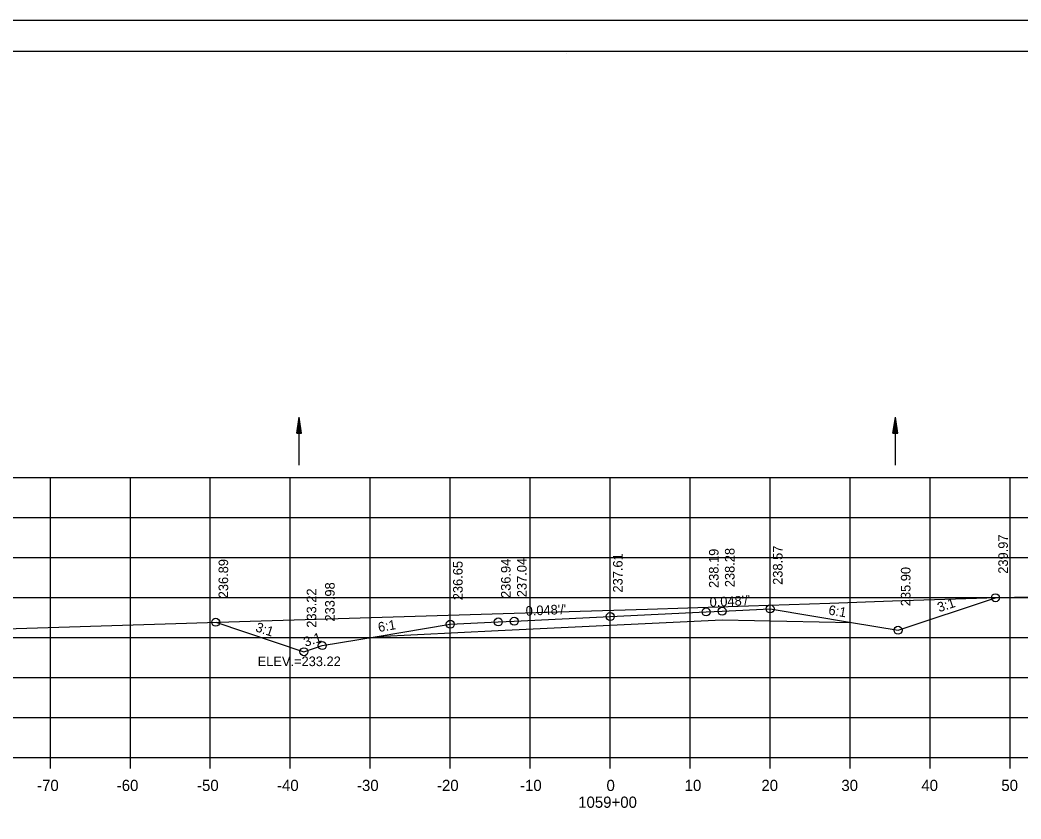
# Model space of a CAD drawing. Extents: x 1386544 to 1388153, y 379785 to 390999.
# Drawn here: x 1387285.9 to 1387411, y 388339 to 388438.9 of the extents above; entities that cross this region are included whole.
import ezdxf

# ---------------------------------------------------------------- set-up
doc = ezdxf.new("R2010")
doc.units = 0
for name, color, linetype in [('R_Alt Surface', 7, 'Continuous'), ('R_Axis', 7, 'Continuous'), ('R_Axis Annot', 7, 'Continuous'), ('R_Border', 7, 'Continuous'), ('R_Exist Surface', 7, 'Continuous'), ('R_Fin Surface', 7, 'Continuous'), ('R_Grid', 7, 'Continuous'), ('R_No Plot', 7, 'Continuous'), ('R_Water', 7, 'Continuous'), ('R_Xsect Elev', 7, 'Continuous'), ('R_Xsect Slope', 7, 'Continuous')]:
    doc.layers.add(name, color=color, linetype=linetype)

msp = doc.modelspace()

# ---------------------------------------------------------------- linework, layer by layer
at = {"layer": 'R_Alt Surface'}
msp.add_lwpolyline([(1387330.55, 388361.83), (1387345.68, 388362.55), (1387359.68, 388363.22), (1387373.68, 388363.9), (1387389.84, 388363.57)], dxfattribs=at)
at = {"layer": 'R_Axis'}
for p, q in [((1387209.68, 388346.7), (1387509.68, 388346.7)), ((1387289.68, 388345.3), (1387289.68, 388346.7)), ((1387299.68, 388345.3), (1387299.68, 388346.7)), ((1387309.68, 388345.3), (1387309.68, 388346.7)), ((1387319.68, 388345.3), (1387319.68, 388346.7)), ((1387329.68, 388345.3), (1387329.68, 388346.7)), ((1387339.68, 388345.3), (1387339.68, 388346.7)), ((1387349.68, 388345.3), (1387349.68, 388346.7)), ((1387359.68, 388345.3), (1387359.68, 388346.7)), ((1387369.68, 388345.3), (1387369.68, 388346.7)), ((1387379.68, 388345.3), (1387379.68, 388346.7)), ((1387389.68, 388345.3), (1387389.68, 388346.7)), ((1387399.68, 388345.3), (1387399.68, 388346.7)), ((1387409.68, 388345.3), (1387409.68, 388346.7))]:
    msp.add_line(p, q, dxfattribs=at)
at = {"layer": 'R_Border'}
for p, q in [((1387201.68, 388434.99), (1387517.86, 388434.99)), ((1387354.2, 388434.73), (1387354.2, 388434.73)), ((1387354.2, 388434.73), (1387354.2, 388434.73))]:
    msp.add_line(p, q, dxfattribs=at)
at = {"layer": 'R_Exist Surface'}
msp.add_lwpolyline([(1387209.68, 388360.51), (1387210.68, 388360.55), (1387229.13, 388361.1), (1387257.28, 388361.92), (1387273.41, 388362.42), (1387314.65, 388363.72), (1387355.93, 388364.97), (1387364.35, 388365.22), (1387374.45, 388365.57), (1387387.13, 388366), (1387394.98, 388366.27), (1387406.76, 388366.63), (1387411.97, 388366.79), (1387413.05, 388366.83), (1387418.4, 388366.99), (1387462.47, 388368.36), (1387498.78, 388369.3), (1387509.68, 388369.55)], dxfattribs=at)
at = {"layer": 'R_Fin Surface'}
msp.add_lwpolyline([(1387310.36, 388363.59), (1387321.38, 388359.91), (1387323.68, 388360.68), (1387330.55, 388361.83), (1387339.68, 388363.35), (1387345.68, 388363.63), (1387347.68, 388363.73), (1387359.68, 388364.31), (1387371.68, 388364.88), (1387373.68, 388364.98), (1387379.68, 388365.27), (1387389.84, 388363.57), (1387395.68, 388362.6), (1387407.86, 388366.66)], dxfattribs=at)
at = {"layer": 'R_Grid'}
for p, q in [((1387209.68, 388381.7), (1387509.68, 388381.7)), ((1387289.68, 388346.7), (1387289.68, 388381.7)), ((1387299.68, 388346.7), (1387299.68, 388381.7)), ((1387309.68, 388346.7), (1387309.68, 388381.7)), ((1387319.68, 388346.7), (1387319.68, 388381.7)), ((1387329.68, 388346.7), (1387329.68, 388381.7)), ((1387339.68, 388346.7), (1387339.68, 388381.7)), ((1387349.68, 388346.7), (1387349.68, 388381.7)), ((1387359.68, 388346.7), (1387359.68, 388381.7)), ((1387369.68, 388346.7), (1387369.68, 388381.7)), ((1387379.68, 388346.7), (1387379.68, 388381.7)), ((1387389.68, 388346.7), (1387389.68, 388381.7)), ((1387399.68, 388346.7), (1387399.68, 388381.7)), ((1387409.68, 388346.7), (1387409.68, 388381.7)), ((1387209.68, 388376.7), (1387509.68, 388376.7)), ((1387209.68, 388371.7), (1387509.68, 388371.7)), ((1387209.68, 388366.7), (1387509.68, 388366.7)), ((1387209.68, 388361.7), (1387509.68, 388361.7)), ((1387209.68, 388356.7), (1387509.68, 388356.7)), ((1387209.68, 388351.7), (1387509.68, 388351.7)), ((1387209.68, 388346.7), (1387509.68, 388346.7))]:
    msp.add_line(p, q, dxfattribs=at)
at = {"layer": 'R_No Plot'}
msp.add_line((1387189.28, 388438.88), (1387522.61, 388438.88), dxfattribs=at)
for points in [[(1387189.27, 388438.88), (1387522.61, 388438.88), (1387522.61, 388225.55), (1387189.27, 388225.55)], [(1387435.6, 388434.99), (1387455.22, 388434.99), (1387455.22, 388425.11), (1387471.33, 388425.11), (1387494.53, 388425.11), (1387494.53, 388400.78), (1387517.86, 388400.78), (1387517.86, 388229.53), (1387201.68, 388229.53), (1387201.68, 388434.99)]]:
    msp.add_lwpolyline(points, close=True, dxfattribs=at)
for centre in [(1387407.86, 388366.66), (1387379.68, 388365.27), (1387359.68, 388364.31), (1387371.68, 388364.88), (1387373.68, 388364.98), (1387310.36, 388363.59), (1387339.68, 388363.35), (1387345.68, 388363.63), (1387347.68, 388363.73), (1387395.68, 388362.6), (1387323.68, 388360.68), (1387321.38, 388359.91)]:
    msp.add_circle(centre, 0.5, dxfattribs=at)
at = {"layer": 'R_Water'}
for p, q in [((1387320.49, 388387.23), (1387320.79, 388389.23)), ((1387320.49, 388387.23), (1387320.79, 388389.23)), ((1387320.54, 388387.23), (1387320.79, 388388.9)), ((1387320.54, 388387.23), (1387320.79, 388388.9)), ((1387320.59, 388387.23), (1387320.79, 388388.55)), ((1387320.59, 388387.23), (1387320.79, 388388.55)), ((1387320.64, 388387.23), (1387320.79, 388388.22)), ((1387320.64, 388387.23), (1387320.79, 388388.22)), ((1387320.79, 388383.23), (1387320.79, 388389.23)), ((1387321.09, 388387.23), (1387320.79, 388389.23)), ((1387321.09, 388387.23), (1387320.79, 388389.23)), ((1387321.04, 388387.23), (1387320.79, 388388.9)), ((1387321.04, 388387.23), (1387320.79, 388388.9)), ((1387320.99, 388387.23), (1387320.79, 388388.55)), ((1387320.99, 388387.23), (1387320.79, 388388.55)), ((1387320.94, 388387.23), (1387320.79, 388388.22)), ((1387320.94, 388387.23), (1387320.79, 388388.22)), ((1387395.04, 388387.23), (1387395.34, 388389.23)), ((1387395.04, 388387.23), (1387395.34, 388389.23)), ((1387395.09, 388387.23), (1387395.34, 388388.9)), ((1387395.09, 388387.23), (1387395.34, 388388.9)), ((1387395.14, 388387.23), (1387395.34, 388388.55)), ((1387395.14, 388387.23), (1387395.34, 388388.55)), ((1387395.19, 388387.23), (1387395.34, 388388.22)), ((1387395.19, 388387.23), (1387395.34, 388388.22)), ((1387395.34, 388383.23), (1387395.34, 388389.23)), ((1387395.64, 388387.23), (1387395.34, 388389.23)), ((1387395.64, 388387.23), (1387395.34, 388389.23)), ((1387395.59, 388387.23), (1387395.34, 388388.9)), ((1387395.59, 388387.23), (1387395.34, 388388.9)), ((1387395.54, 388387.23), (1387395.34, 388388.55)), ((1387395.54, 388387.23), (1387395.34, 388388.55)), ((1387395.49, 388387.23), (1387395.34, 388388.22)), ((1387395.49, 388387.23), (1387395.34, 388388.22)), ((1387320.49, 388387.23), (1387321.09, 388387.23)), ((1387320.49, 388387.23), (1387321.09, 388387.23)), ((1387320.69, 388387.23), (1387320.79, 388387.88)), ((1387320.69, 388387.23), (1387320.79, 388387.88)), ((1387320.74, 388387.23), (1387320.79, 388387.55)), ((1387320.74, 388387.23), (1387320.79, 388387.55)), ((1387320.89, 388387.23), (1387320.79, 388387.88)), ((1387320.89, 388387.23), (1387320.79, 388387.88)), ((1387320.84, 388387.23), (1387320.79, 388387.55)), ((1387320.84, 388387.23), (1387320.79, 388387.55)), ((1387395.04, 388387.23), (1387395.64, 388387.23)), ((1387395.04, 388387.23), (1387395.64, 388387.23)), ((1387395.25, 388387.23), (1387395.34, 388387.88)), ((1387395.25, 388387.23), (1387395.34, 388387.88)), ((1387395.3, 388387.23), (1387395.34, 388387.55)), ((1387395.3, 388387.23), (1387395.34, 388387.55)), ((1387395.44, 388387.23), (1387395.34, 388387.88)), ((1387395.44, 388387.23), (1387395.34, 388387.88)), ((1387395.39, 388387.23), (1387395.34, 388387.55)), ((1387395.39, 388387.23), (1387395.34, 388387.55))]:
    msp.add_line(p, q, dxfattribs=at)

# ---------------------------------------------------------------- texts
at = {"layer": 'R_Axis Annot'}
for s, p in [('-70', (1387288.02, 388342.5)), ('-60', (1387297.98, 388342.5)), ('-50', (1387308.02, 388342.5)), ('-40', (1387318.02, 388342.5)), ('-30', (1387328.02, 388342.5)), ('-20', (1387338.02, 388342.5)), ('-10', (1387348.41, 388342.5)), ('0', (1387359.22, 388342.5)), ('10', (1387368.99, 388342.5)), ('20', (1387378.59, 388342.5)), ('30', (1387388.59, 388342.5)), ('40', (1387398.59, 388342.5)), ('50', (1387408.59, 388342.5)), ('1059+00', (1387355.68, 388340.4))]:
    msp.add_text(s, height=1.4, dxfattribs=at).set_placement(p)
at = {"layer": 'R_Xsect Elev'}
for s, p in [('239.97', (1387409.41, 388369.66)), ('238.57', (1387381.23, 388368.27)), ('237.61', (1387361.23, 388367.31)), ('238.19', (1387373.23, 388367.88)), ('238.28', (1387375.23, 388367.98)), ('236.89', (1387311.91, 388366.59)), ('236.65', (1387341.23, 388366.35)), ('236.94', (1387347.23, 388366.63)), ('237.04', (1387349.23, 388366.73)), ('235.90', (1387397.23, 388365.6)), ('233.98', (1387325.23, 388363.68)), ('233.22', (1387322.93, 388362.91))]:
    msp.add_text(s, height=1.2, rotation=90, dxfattribs=at).set_placement(p)
msp.add_text('ELEV.=233.22', height=1.2, dxfattribs=at).set_placement((1387315.6, 388358.11))
at = {"layer": 'R_Xsect Slope'}
for s, rotation, p in [("0.048'/'", 2.7481, (1387372.14, 388365.51)), ("0.048'/'", 2.7481, (1387349.14, 388364.4)), ('6:1', 350.5377, (1387386.91, 388364.57)), ('3:1', 18.4349, (1387400.82, 388364.84)), ('3:1', 341.5651, (1387315.24, 388362.49)), ('6:1', 9.4623, (1387330.75, 388362.37)), ('3:1', 18.4349, (1387321.58, 388360.51))]:
    msp.add_text(s, height=1.2, rotation=rotation, dxfattribs=at).set_placement(p)

doc.saveas('drawing.dxf')
